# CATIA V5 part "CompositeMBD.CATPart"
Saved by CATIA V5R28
Part number: Composite MBD
Bounding box of the stored display mesh (mm): x -54 to 96, y -104.114 to 14.853, z -24.35 to 72.398
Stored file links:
  C:\Users\jvl2147\Documents\2CES-COEXISTENCE\CompositeMBD.CATPart
  C:\Users\jvl2147\Documents\ASME Y14.37\PartExamples\ASME-Y14.37_COMPOSITES-A.CATMaterial
  C:\Program Files\Dassault Systemes\B28SP3PRALL\win_b64\startup\composites\LaminateColors.txt
  C:\Program Files\Dassault Systemes\B28SP3PRALL\win_b64\startup\composites\DropOffPattern1BackSlash.txt
  C:\Program Files\Dassault Systemes\B28SP3PRALL\win_b64\startup\composites\DropOffPattern1Backslash.txt
  C:\Program Files\Dassault Systemes\B28SP3PRALL\win_b64\startup\composites\DropOffPattern1InverseV.txt
  C:\Program Files\Dassault Systemes\B28SP3PRALL\win_b64\startup\composites\DropOffPattern1InverseW.txt
  C:\Program Files\Dassault Systemes\B28SP3PRALL\win_b64\startup\composites\DropOffPattern1Slash.txt
  C:\Program Files\Dassault Systemes\B28SP3PRALL\win_b64\startup\composites\DropOffPattern1V.txt
  C:\Program Files\Dassault Systemes\B28SP3PRALL\win_b64\startup\composites\DropOffPattern1V_Symetry.txt
  C:\Program Files\Dassault Systemes\B28SP3PRALL\win_b64\startup\composites\DropOffPattern1V_Symetry_2Consecutive.txt
  C:\Program Files\Dassault Systemes\B28SP3PRALL\win_b64\startup\composites\DropOffPattern1W.txt
  C:\Program Files\Dassault Systemes\B28SP3PRALL\win_b64\startup\composites\DropOffPattern2Cross.txt
  C:\Program Files\Dassault Systemes\B28SP3PRALL\win_b64\startup\composites\DropOffPattern2Diamond.txt
  C:\Program Files\Dassault Systemes\B28SP3PRALL\win_b64\startup\composites\DropOffPattern2Socks.txt
  C:\Program Files\Dassault Systemes\B28SP3PRALL\win_b64\startup\composites\DropOffPattern45AfterOthers.txt
  C:\Program Files\Dassault Systemes\B28SP3PRALL\win_b64\startup\composites\DropOffPattern4TwinDiamonds45.txt
  C:\Program Files\Dassault Systemes\B28SP3PRALL\win_b64\startup\composites\DropOffPattern5Cross_Pseudo_Sym.txt
  C:\Program Files\Dassault Systemes\B28SP3PRALL\win_b64\startup\composites\DropOffPattern5Diamond_Pseudo_Sym.txt
  C:\Program Files\Dassault Systemes\B28SP3PRALL\win_b64\startup\composites\DropOffPattern5Socks_Pseudo_Sym.txt
  C:\Users\jvl2147\Desktop\LaserExportTest.ply
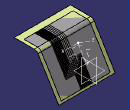
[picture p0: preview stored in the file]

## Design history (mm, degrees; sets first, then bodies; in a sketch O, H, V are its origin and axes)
Parameters
  `MBD Version - 787N4-1115 Rev` = "A"
AxisSystem1: origin (0, -29.9559, 49.1095), X (1, 0, 0), Y (0, 0.5207, -0.8537), Z (0, 0.8537, 0.5207)
Set1
  Sketch1 on yz-plane, origin (0, 0, 0), H (0, 1, 0), V (0, 0, 1)
    line L1 (-104.1144, 72.3983) -> (-50.835, 72.3983)
    line L2 (-40.6865, 66.7012) -> (14.853, -24.35)
    arc A1 centre (-50.835, 60.5109) radius 11.8875 from (-50.835, 72.3983) to (-40.6865, 66.7012) cw
    radius A1 = 11.8875
    horizontal: L1 H
    coincidence: L2 O
    tangency: A1 L1, A1 L2
  Extrude1: Element1 Sketch1, Lim1 96, Lim2 54
  Plane1: type Offset, RefPlane yz-plane, Offset 87
  Plane2: type Offset, RefPlane yz-plane, Offset 44, reversed
  Plane3: type Offset, RefPlane zx-plane, Offset -87
  Plane4: type Offset, RefPlane xy-plane, Offset -20
  MultiSel1
  Point1: type OnCurve, Support Sketch1, Ratio 0.5
  Line1: type Normal, RefPoint Point1, RefSkin Extrude1, Start 0, End 20
  Plane5: type Offset, RefPlane ZX plane of AxisSystem1, Offset 20
Set2 "Ply Group - Boeing MBD"
  Set3 "Ply Group Definition Data"
    AxisSystem2 "Rosette": origin (0, -29.9559, 49.1095), X (1, 0, 0), Y (0, 0.5207, -0.8537), Z (0, 0.8537, 0.5207)
    DatumSurface1 "Definition Surface": linked copy from another document
  Set4 "SEQUENCE S10"
    Set5 "PLY P1", material "10721"
      DatumSurface2 "Geometry_1"
  Set6 "SEQUENCE S20"
    Set7 "PLY P2", material "10721"
      DatumSurface3 "Geometry_2"
  Set8 "SEQUENCE S30"
    Set9 "PLY P3", material "10721"
      DatumSurface4 "Geometry_3"
  Set10 "SEQUENCE S40"
    Set11 "PLY P4", material "10721"
      DatumSurface5 "Geometry_4"
  Set12 "SEQUENCE S50"
    Set13 "PLY P5", material "10721"
      DatumSurface6 "Geometry_5"
  Set14 "SEQUENCE S60"
    Set15 "PLY P6", material "10721"
      DatumSurface7 "Geometry_6"
  Set16 "SEQUENCE S70"
    Set17 "PLY P7", material "10721"
      DatumSurface8 "Geometry_7"
  Set18 "SEQUENCE S80"
    Set19 "PLY P8", material "10721"
      DatumSurface9 "Geometry_8"
  Set20 "SEQUENCE S90"
    Set21 "PLY P9", material "10721"
      DatumSurface10 "Geometry_9"
  Set22 "SEQUENCE S100"
    Set23 "PLY P10", material "10721"
      DatumSurface11 "Geometry_10"
  Set24 "SEQUENCE S110"
    Set25 "PLY P11", material "10721"
      DatumSurface12 "Geometry_11"
  Set26 "SEQUENCE S120"
    Set27 "PLY P12", material "10721"
      DatumSurface13 "Geometry_12"
  Set28 "SEQUENCE S130"
    Set29 "PLY P13", material "10721"
      DatumSurface14 "Geometry_13"
  Set30 "SEQUENCE S140"
    Set31 "PLY P14", material "10721"
      DatumSurface15 "Geometry_14"
  Set32 "SEQUENCE S150"
    Set33 "PLY P15", material "10721"
      DatumSurface16 "Geometry_15"
  Set34 "SEQUENCE S160"
    Set35 "PLY P16", material "10721"
      DatumSurface17 "Geometry_16"
  Set36 "SEQUENCE S170"
    Set37 "PLY P17", material "10721"
      DatumSurface18 "Geometry_17"
  Set38 "SEQUENCE S180"
    Set39 "PLY P18", material "10721"
      DatumSurface19 "Geometry_18"
  Set40 "SEQUENCE S190"
    Set41 "PLY P19", material "10721"
      DatumSurface20 "Geometry_19"
  Set42 "SEQUENCE S200"
    Set43 "PLY P20", material "10721"
      DatumSurface21 "Geometry_20"
  Set44 "SEQUENCE S210"
    Set45 "PLY P21", material "10721"
      DatumSurface22 "Geometry_21"
  Set46 "SEQUENCE S220"
    Set47 "PLY P22", material "10721"
      DatumSurface23 "Geometry_22"
  Set48 "SEQUENCE S230"
    Set49 "PLY P23", material "10721"
      DatumSurface24 "Geometry_23"
  Set50 "SEQUENCE S240"
    Set51 "PLY P24", material "10721"
      DatumSurface25 "Geometry_24"
  Set52 "SEQUENCE S250"
    Set53 "PLY P25", material "10721"
      DatumSurface26 "Geometry_25"
  Set54 "SEQUENCE S260"
    Set55 "PLY P26", material "10721"
      DatumSurface27 "Geometry_26"
  Set56 "SEQUENCE S270"
    Set57 "PLY P27", material "10721"
      DatumSurface28 "Geometry_27"
  Set58 "SEQUENCE S280"
    Set59 "PLY P28", material "10721"
      DatumSurface29 "Geometry_28"
  Set60 "SEQUENCE S290"
    Set61 "PLY P29", material "10721"
      DatumSurface30 "Geometry_29"
  Set62 "SEQUENCE S300"
    Set63 "PLY P30", material "10721"
      DatumSurface31 "Geometry_30"
  Set64 "SEQUENCE S310"
    Set65 "PLY P31", material "10721"
      DatumSurface32 "Geometry_31"
  Set66 "SEQUENCE S320"
    Set67 "PLY P32", material "10721"
      DatumSurface33 "Geometry_32"
Body1 (main body)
